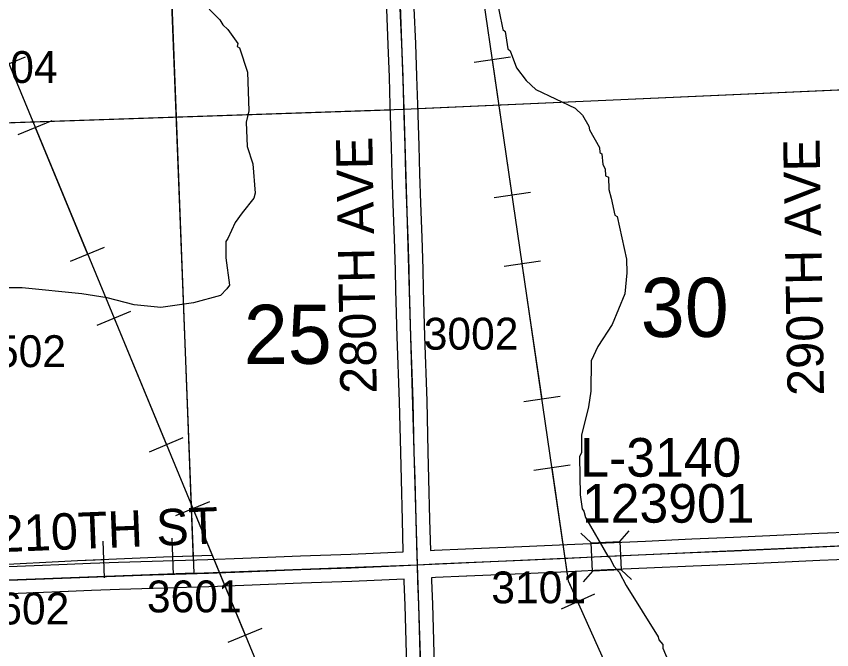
# Model space of a CAD drawing. Extents: x 128.7 to 185.5, y -21.4 to 12.6.
# Drawn here: x 151.274 to 153.067, y -6.33 to -4.937 of the extents above; entities that cross this region are included whole.
import ezdxf

# ---------------------------------------------------------------- set-up
doc = ezdxf.new("R2010")
doc.units = 0
for name, color, linetype in [('tdCoHydroRiver', 7, 'Continuous'), ('tdCoPipe', 7, 'Continuous'), ('tdCoSecRdNmbr', 7, 'Continuous'), ('tdCoSecRdTxt', 7, 'Continuous'), ('tdCoSecRteBand', 7, 'Continuous'), ('tdCoSecRteCL', 7, 'Continuous'), ('tdCoSectLine', 7, 'Continuous'), ('tdCoSectLinePart', 7, 'Continuous'), ('tdCoSectNmbr', 7, 'Continuous'), ('tdCoStrucSec', 7, 'Continuous'), ('tdCoStrucSecCoName', 7, 'Continuous'), ('tdCoStrucSecFHWANum', 7, 'Continuous'), ('tdCoSurfGravel', 7, 'Continuous'), ('tdCoTwpBndry', 7, 'Continuous'), ('tdCoTwpBndryShd', 7, 'Continuous')]:
    doc.layers.add(name, color=color, linetype=linetype)

msp = doc.modelspace()

# ---------------------------------------------------------------- linework, layer by layer
at = {"layer": 'tdCoHydroRiver'}
for points in [[(152.3193, -4.8469), (152.3439, -4.966), (152.3488, -4.9706), (152.3548, -5.0082), (152.3597, -5.0128), (152.3736, -5.0502), (152.3951, -5.0779), (152.4163, -5.0977), (152.5029, -5.1389), (152.5192, -5.1541), (152.5327, -5.1789), (152.5346, -5.1867), (152.5564, -5.2254), (152.5568, -5.2364), (152.5616, -5.2394), (152.564, -5.263), (152.5691, -5.2723), (152.5696, -5.2881), (152.576, -5.291), (152.577, -5.3178), (152.5823, -5.3366), (152.5899, -5.3742), (152.5948, -5.3772), (152.6154, -5.4712), (152.6164, -5.5011), (152.6117, -5.547), (152.584, -5.6143), (152.5525, -5.6627), (152.5378, -5.6948), (152.5372, -5.761), (152.5322, -5.7959), (152.5171, -5.8579), (152.517, -5.8957), (152.5126, -5.9053), (152.5141, -5.9889), (152.5185, -6.0202), (152.5219, -6.0248), (152.5256, -6.0389), (152.5748, -6.1238), (152.5781, -6.1269), (152.5884, -6.147), (152.5998, -6.1592), (152.6151, -6.1887), (152.6852, -6.3015), (152.687, -6.3077), (152.6953, -6.3185), (152.6955, -6.3264), (152.7093, -6.3591)], [(151.6755, -4.8974), (151.7214, -4.9448), (151.728, -4.9556), (151.7394, -4.9662), (151.761, -4.9971), (151.7597, -5.0034), (151.7645, -5.0064), (151.7821, -5.0595), (151.785, -5.1446), (151.7796, -5.17), (151.7814, -5.2236), (151.7938, -5.2611), (151.7991, -5.3256), (151.7964, -5.3368), (151.7707, -5.3692), (151.7556, -5.3902), (151.7394, -5.4255), (151.7349, -5.432), (151.7346, -5.4683), (151.743, -5.528), (151.7369, -5.5361), (151.7232, -5.5508), (151.6638, -5.567), (151.5916, -5.5774), (151.533, -5.5715), (151.4741, -5.5562), (151.4185, -5.547), (151.2871, -5.5342), (151.246, -5.534)]]:
    msp.add_lwpolyline(points, dxfattribs=at)
at = {"layer": 'tdCoPipe'}
for p, q in [((151.2201, -5.0566), (151.2946, -5.0258)), ((152.3609, -5.0267), (152.2811, -5.0383)), ((151.2783, -5.1972), (151.3526, -5.1664)), ((152.4044, -5.3247), (152.3248, -5.3363)), ((151.3934, -5.4754), (151.4679, -5.4446)), ((152.4264, -5.4752), (152.3466, -5.4869)), ((151.4516, -5.616), (151.526, -5.5852)), ((152.4699, -5.7732), (152.3903, -5.7848)), ((151.5668, -5.8943), (151.6413, -5.8634)), ((152.4919, -5.9237), (152.4121, -5.9354)), ((151.6249, -6.0348), (151.6993, -6.004)), ((151.4683, -6.1714), (151.4648, -6.0908)), ((151.62, -6.165), (151.617, -6.0845)), ((152.5452, -6.2073), (152.4718, -6.2402)), ((151.7401, -6.3131), (151.8146, -6.2822))]:
    msp.add_line(p, q, dxfattribs=at)
for points in [[(153.2907, -13.3487), (153.1504, -13.0403), (153.08, -11.9742), (153.9221, -10.7441), (153.8422, -9.1961), (152.4885, -6.1792), (152.255, -4.5804), (152.0586, -4.5041), (150.9187, -1.6917), (149.9982, 2.3236), (149.759, 2.5022), (149.1601, 4.9961)], [(148.6284, 1.2813), (148.7667, 0.7397), (148.8239, 0.5169), (149.0454, 0.2655), (149.1111, 0.0311), (149.7815, -1.9917), (149.8869, -2.2086), (150.0884, -2.36), (150.353, -3.1907), (150.6682, -4.2821), (150.7734, -4.4455), (150.8791, -4.6209), (150.9399, -4.7309), (150.9845, -4.7883), (151.1763, -4.8453), (151.8715, -6.5252), (151.9475, -6.6623), (151.9951, -7.1544), (151.9928, -7.2474), (152.3334, -7.551)], [(152.3645, -5.3305), (152.321, -5.0325)], [(151.3155, -5.1818), (151.4307, -5.46)], [(152.43, -5.779), (152.3865, -5.481)], [(151.4889, -5.6006), (151.604, -5.8788)], [(152.5084, -6.2238), (152.4885, -6.1792), (152.452, -5.9295)], [(151.6622, -6.0194), (151.7774, -6.2976)], [(141.1601, -9.4052), (141.1224, -8.4625), (145.143, -8.3469), (145.1432, -8.4836), (145.1432, -8.4836), (147.1541, -8.3987), (147.1541, -8.3987), (147.1261, -7.4066), (149.2539, -7.3111), (149.2196, -6.4561), (150.4341, -6.4227), (150.6653, -6.4146), (150.7655, -6.4047), (150.7905, -6.3931), (150.9328, -6.2039), (151.0021, -6.1768), (151.0811, -6.1651), (151.2121, -6.1436), (151.4086, -6.1336), (151.5974, -6.1255), (151.7034, -6.1214)], [(151.6185, -6.1247), (151.7034, -6.1214)], [(151.1663, -6.1511), (151.2121, -6.1436), (151.4086, -6.1336), (151.4665, -6.1311)]]:
    msp.add_lwpolyline(points, dxfattribs=at)
at = {"layer": 'tdCoSecRteBand'}
for points in [[(151.2567, -6.1465), (151.3134, -6.1443), (151.3134, -6.1443), (151.3134, -6.1443), (151.3858, -6.1416), (151.4369, -6.1392), (151.4371, -6.1391), (151.4374, -6.1391), (151.499, -6.1372), (151.5727, -6.1347), (151.5728, -6.1347), (151.5728, -6.1347), (151.6953, -6.131), (151.7724, -6.1283), (151.8988, -6.1234), (151.8989, -6.1234), (151.8989, -6.1234), (152.0093, -6.1194), (152.1242, -6.1145), (152.125, -6.1145), (152.125, -6.1138), (152.125, -6.1138), (152.1229, -6.0451), (152.1229, -6.045), (152.1229, -6.0449), (152.1207, -5.9557), (152.1207, -5.9557), (152.1207, -5.9557), (152.1192, -5.8957), (152.1192, -5.8957), (152.1192, -5.8957), (152.1165, -5.7839), (152.1118, -5.642), (152.1118, -5.6419), (152.1118, -5.6419), (152.1089, -5.5383), (152.1089, -5.5383), (152.1089, -5.5383), (152.1076, -5.4949), (152.1054, -5.4254), (152.1029, -5.35), (152.1007, -5.2854), (152.1007, -5.2853), (152.1007, -5.2852), (152.099, -5.2237), (152.096, -5.1327), (152.096, -5.1327), (152.096, -5.1326), (152.0943, -5.0711), (152.0916, -4.9995), (152.0884, -4.9211)], [(152.1484, -4.9189), (152.1516, -4.9971), (152.1516, -4.9972), (152.1516, -4.9972), (152.1543, -5.069), (152.1543, -5.0691), (152.1543, -5.0693), (152.156, -5.1308), (152.159, -5.2218), (152.159, -5.2218), (152.159, -5.2219), (152.1607, -5.2835), (152.1629, -5.348), (152.1629, -5.348), (152.1629, -5.348), (152.1654, -5.4235), (152.1654, -5.4235), (152.1654, -5.4235), (152.1676, -5.4931), (152.1676, -5.4931), (152.1676, -5.4932), (152.1688, -5.5366), (152.1718, -5.6401), (152.1765, -5.7821), (152.1765, -5.7822), (152.1765, -5.7823), (152.1792, -5.8943), (152.1807, -5.9542), (152.1829, -6.0434), (152.185, -6.1112)], [(152.185, -6.1112), (152.1931, -6.1108), (152.1933, -6.1108), (152.1935, -6.1108), (152.2618, -6.1081), (152.3857, -6.1029), (152.485, -6.0982), (152.485, -6.0982), (152.4851, -6.0982), (152.5709, -6.0943), (152.5709, -6.0943), (152.571, -6.0943), (152.6575, -6.0906), (152.7593, -6.0861), (152.7594, -6.0861), (152.7594, -6.0861), (152.8508, -6.0822), (152.9309, -6.0785), (152.9309, -6.0785), (152.9309, -6.0785), (153.0382, -6.0736), (153.0382, -6.0736), (153.0383, -6.0736), (153.1137, -6.0703)], [(153.1157, -6.1302), (153.0409, -6.1335), (152.9337, -6.1384), (152.8535, -6.1421), (152.8535, -6.1421), (152.8534, -6.1421), (152.762, -6.1461), (152.6601, -6.1505), (152.6601, -6.1505), (152.6601, -6.1505), (152.5736, -6.1542), (152.4878, -6.1582), (152.3885, -6.1628), (152.3884, -6.1628), (152.3883, -6.1628), (152.2643, -6.168), (152.2642, -6.168), (152.2642, -6.168), (152.1961, -6.1707), (152.1875, -6.1712), (152.1869, -6.1712), (152.1871, -6.1776), (152.1888, -6.2296), (152.1888, -6.2297), (152.1888, -6.2297), (152.1913, -6.3096), (152.1913, -6.3097), (152.1913, -6.3099), (152.1925, -6.3642)], [(152.1325, -6.3657), (152.1313, -6.3113), (152.1288, -6.2316), (152.1271, -6.1796), (152.1271, -6.1796), (152.1271, -6.1796), (152.1269, -6.1744), (152.1269, -6.1744), (152.0118, -6.1794), (152.0117, -6.1794), (152.0115, -6.1794), (151.9011, -6.1833), (151.7747, -6.1882), (151.7746, -6.1883), (151.7745, -6.1883), (151.6974, -6.191), (151.6973, -6.191), (151.6972, -6.191), (151.5747, -6.1947), (151.501, -6.1971), (151.501, -6.1971), (151.501, -6.1971), (151.4396, -6.1991), (151.3885, -6.2016), (151.3883, -6.2016), (151.3882, -6.2016), (151.3157, -6.2043), (151.2593, -6.2065)]]:
    msp.add_lwpolyline(points, dxfattribs=at)
at = {"layer": 'tdCoSecRteCL'}
for points in [[(152.1559, -6.1428), (152.1554, -6.1248), (152.1529, -6.0442), (152.1507, -5.9549), (152.1492, -5.895), (152.1465, -5.783), (152.1418, -5.641), (152.1388, -5.5374), (152.1376, -5.494), (152.1354, -5.4245), (152.1329, -5.349), (152.1307, -5.2844), (152.129, -5.2228), (152.126, -5.1318), (152.1243, -5.0701), (152.1216, -4.9983), (152.1184, -4.9199)], [(152.1559, -6.1428), (152.1947, -6.1408), (152.263, -6.138), (152.387, -6.1329), (152.4864, -6.1282), (152.5722, -6.1242), (152.6588, -6.1205), (152.7607, -6.1161), (152.8521, -6.1122), (152.9323, -6.1085), (153.0396, -6.1035), (153.1244, -6.0998), (153.1448, -6.0984)], [(151.1597, -6.1803), (151.1804, -6.1797), (151.2243, -6.1785), (151.2578, -6.1765), (151.3146, -6.1743), (151.3871, -6.1716), (151.4384, -6.1691), (151.5, -6.1671), (151.5737, -6.1647), (151.6963, -6.161), (151.7735, -6.1583), (151.9, -6.1533), (152.0105, -6.1494), (152.1256, -6.1445), (152.1559, -6.1428)], [(152.1938, -7.3088), (152.1914, -7.2333), (152.1887, -7.1645), (152.185, -7.0634), (152.1835, -7.0097), (152.1813, -6.9357), (152.1793, -6.8735), (152.1758, -6.7848), (152.1744, -6.7458), (152.1716, -6.6706), (152.1699, -6.6092), (152.167, -6.5029), (152.1657, -6.4587), (152.1625, -6.365), (152.1613, -6.3105), (152.1588, -6.2306), (152.1571, -6.1786), (152.1559, -6.1428)]]:
    msp.add_lwpolyline(points, dxfattribs=at)
at = {"layer": 'tdCoSectLine'}
for points in [[(152.091, -4.1427), (152.1259, -5.1413)], [(152.1259, -5.1413), (153.1129, -5.097)], [(151.1319, -5.1749), (152.1259, -5.1413)], [(152.1259, -5.1413), (152.1556, -6.1428)], [(152.1556, -6.1428), (153.1445, -6.0984)], [(151.1593, -6.1803), (152.1556, -6.1428)], [(152.1556, -6.1428), (152.1881, -7.1424)]]:
    msp.add_lwpolyline(points, dxfattribs=at)
at = {"layer": 'tdCoSectLinePart'}
for points in [[(152.1561, -5.1399), (153.0832, -5.0984)], [(151.1623, -5.1739), (152.0962, -5.1423)]]:
    msp.add_lwpolyline(points, dxfattribs=at)
at = {"layer": 'tdCoStrucSec'}
for p, q in [((152.5383, -6.0944), (152.5152, -6.0734)), ((152.6008, -6.0916), (152.6219, -6.0684)), ((152.5412, -6.157), (152.5201, -6.1801)), ((152.6037, -6.1541), (152.6268, -6.1752))]:
    msp.add_line(p, q, dxfattribs=at)
msp.add_lwpolyline([(152.5383, -6.0944), (152.6008, -6.0916), (152.6037, -6.1541), (152.5412, -6.157)], close=True, dxfattribs=at)
at = {"layer": 'tdCoSurfGravel'}
for points in [[(152.126, -5.1318), (152.1243, -5.0701), (152.1216, -4.9983), (152.1184, -4.9199), (152.1154, -4.8161), (152.1117, -4.7231), (152.1097, -4.645), (152.1065, -4.5833), (152.1048, -4.5123), (152.0994, -4.3774), (152.0964, -4.3032), (152.0935, -4.2077), (152.0914, -4.1427)], [(152.1559, -6.1428), (152.1554, -6.1248), (152.1529, -6.0442), (152.1507, -5.9549), (152.1492, -5.895), (152.1465, -5.783), (152.1418, -5.641), (152.1388, -5.5374), (152.1376, -5.494), (152.1354, -5.4245), (152.1329, -5.349), (152.1307, -5.2844), (152.129, -5.2228), (152.126, -5.1318)], [(152.1559, -6.1428), (152.1947, -6.1408), (152.263, -6.138), (152.387, -6.1329), (152.4864, -6.1282), (152.5722, -6.1242), (152.6588, -6.1205), (152.7607, -6.1161), (152.8521, -6.1122), (152.9323, -6.1085), (153.0396, -6.1035), (153.1244, -6.0998), (153.1448, -6.0984)], [(151.1597, -6.1803), (151.1804, -6.1797), (151.2243, -6.1785), (151.2578, -6.1765), (151.3146, -6.1743), (151.3871, -6.1716), (151.4384, -6.1691), (151.5, -6.1671), (151.5737, -6.1647), (151.6963, -6.161), (151.7735, -6.1583), (151.9, -6.1533), (152.0105, -6.1494), (152.1256, -6.1445), (152.1559, -6.1428)], [(152.1938, -7.3088), (152.1914, -7.2333), (152.1887, -7.1645), (152.185, -7.0634), (152.1835, -7.0097), (152.1813, -6.9357), (152.1793, -6.8735), (152.1758, -6.7848), (152.1744, -6.7458), (152.1716, -6.6706), (152.1699, -6.6092), (152.167, -6.5029), (152.1657, -6.4587), (152.1625, -6.365), (152.1613, -6.3105), (152.1588, -6.2306), (152.1571, -6.1786), (152.1559, -6.1428)]]:
    msp.add_lwpolyline(points, dxfattribs=at)
at = {"layer": 'tdCoTwpBndry'}
msp.add_lwpolyline([(151.6639, -6.1347), (151.5896, -4.1993)], dxfattribs=at)
at = {"layer": 'tdCoTwpBndryShd'}
msp.add_lwpolyline([(152.091, -4.1427), (151.586, -4.1605), (151.6647, -6.1613), (151.1593, -6.1803), (150.1506, -6.2319), (149.152, -6.2482), (149.1912, -7.251)], dxfattribs=at)

# ---------------------------------------------------------------- texts
at = {"layer": 'tdCoSecRdNmbr'}
for s, rotation, p in [('2404', 0.1147, (151.1567, -5.0838)), ('3002', 0.1155, (152.17, -5.67)), ('2502', 0.1147, (151.1752, -5.7086)), ('3101', 0.1155, (152.3185, -6.2277)), ('3601', 0.115, (151.5614, -6.2476)), ('3602', 0.1147, (151.1825, -6.2742))]:
    msp.add_text(s, height=0.07, rotation=rotation, dxfattribs=at).set_placement(p)
at = {"layer": 'tdCoSecRdTxt'}
for s, rotation, p in [('280TH AVE', 91, (152.0667, -5.7663)), ('290TH AVE', 91, (153.0499, -5.7708)), ('210TH ST', 2.3175, (151.2327, -6.1155))]:
    msp.add_text(s, height=0.08, rotation=rotation, dxfattribs=at).set_placement(p)
at = {"layer": 'tdCoSectNmbr'}
for s, rotation, p in [('30', 0.1158, (152.6471, -5.6422)), ('25', 0.115, (151.7744, -5.7014))]:
    msp.add_text(s, height=0.13, rotation=rotation, dxfattribs=at).set_placement(p)
at = {"layer": 'tdCoStrucSecCoName'}
msp.add_text('L-3140', height=0.085, dxfattribs=at).set_placement((152.514, -5.9492))
at = {"layer": 'tdCoStrucSecFHWANum'}
msp.add_text('123901', height=0.085, dxfattribs=at).set_placement((152.5178, -6.0503))

doc.saveas('drawing.dxf')
